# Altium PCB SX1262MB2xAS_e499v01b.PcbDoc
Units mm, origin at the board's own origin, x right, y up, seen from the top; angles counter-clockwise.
Board outline 65 x 53.3 mm, 4 copper layers (Top Layer, MidLayer1, MidLayer2, Bottom Layer), stack 0.986 mm thick; 64 components, 41 nets, 172 pads, 838 vias.
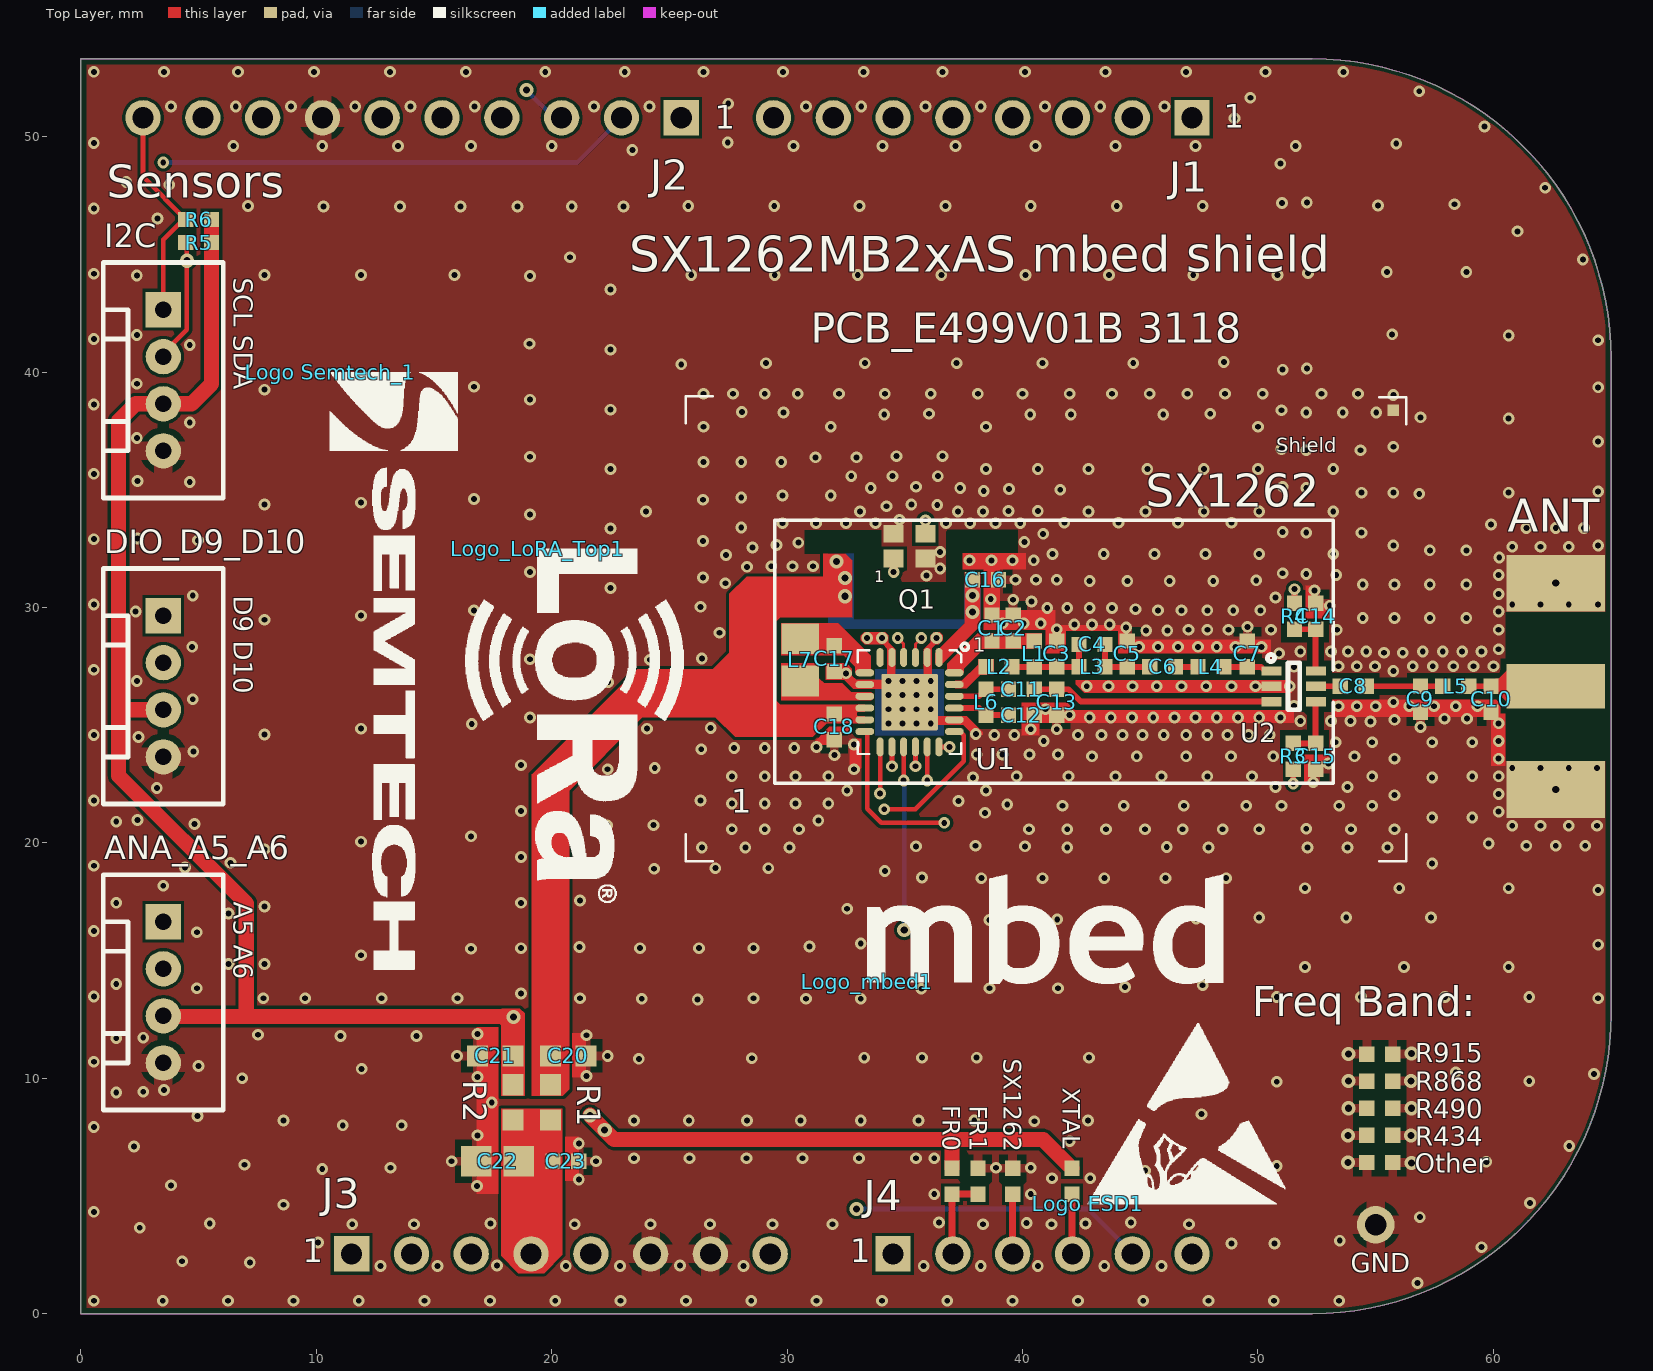
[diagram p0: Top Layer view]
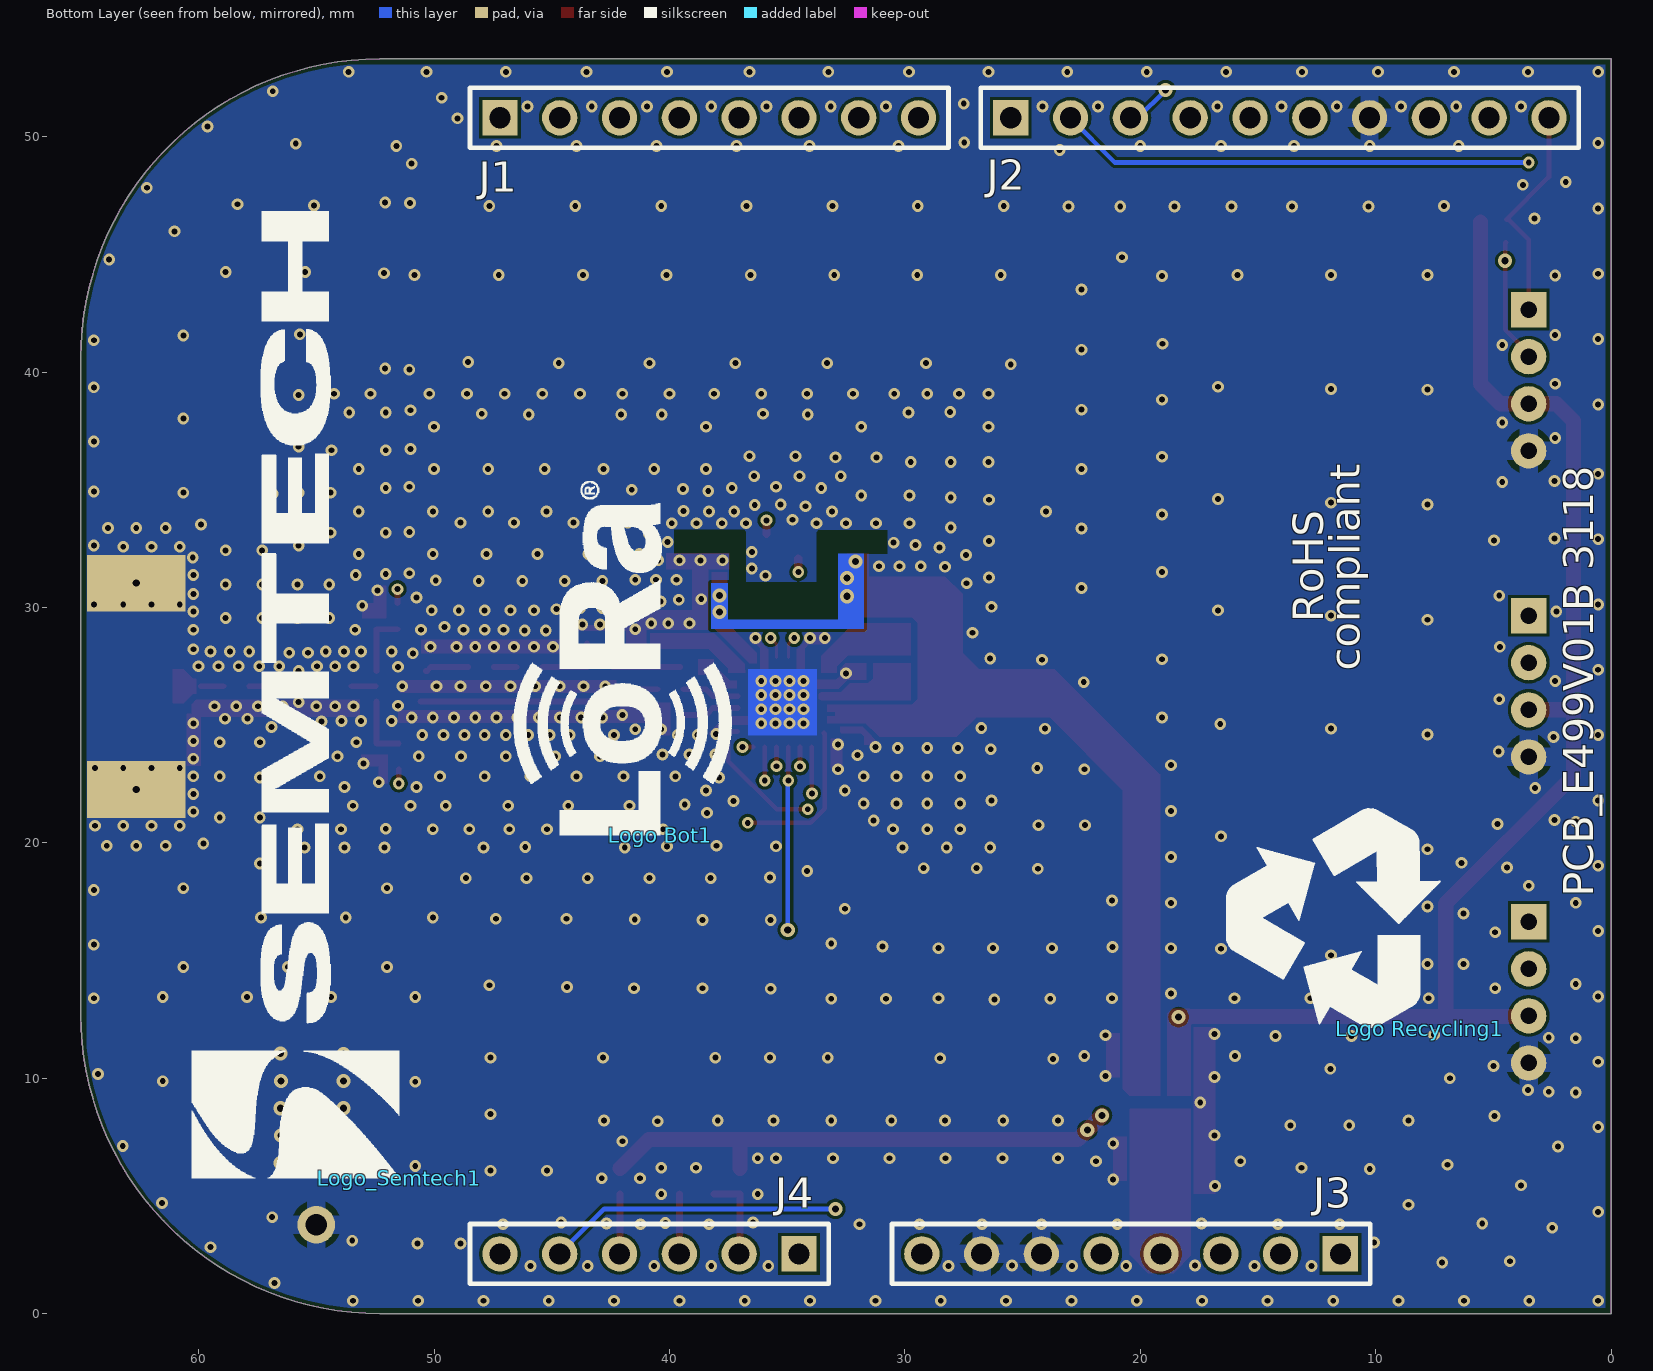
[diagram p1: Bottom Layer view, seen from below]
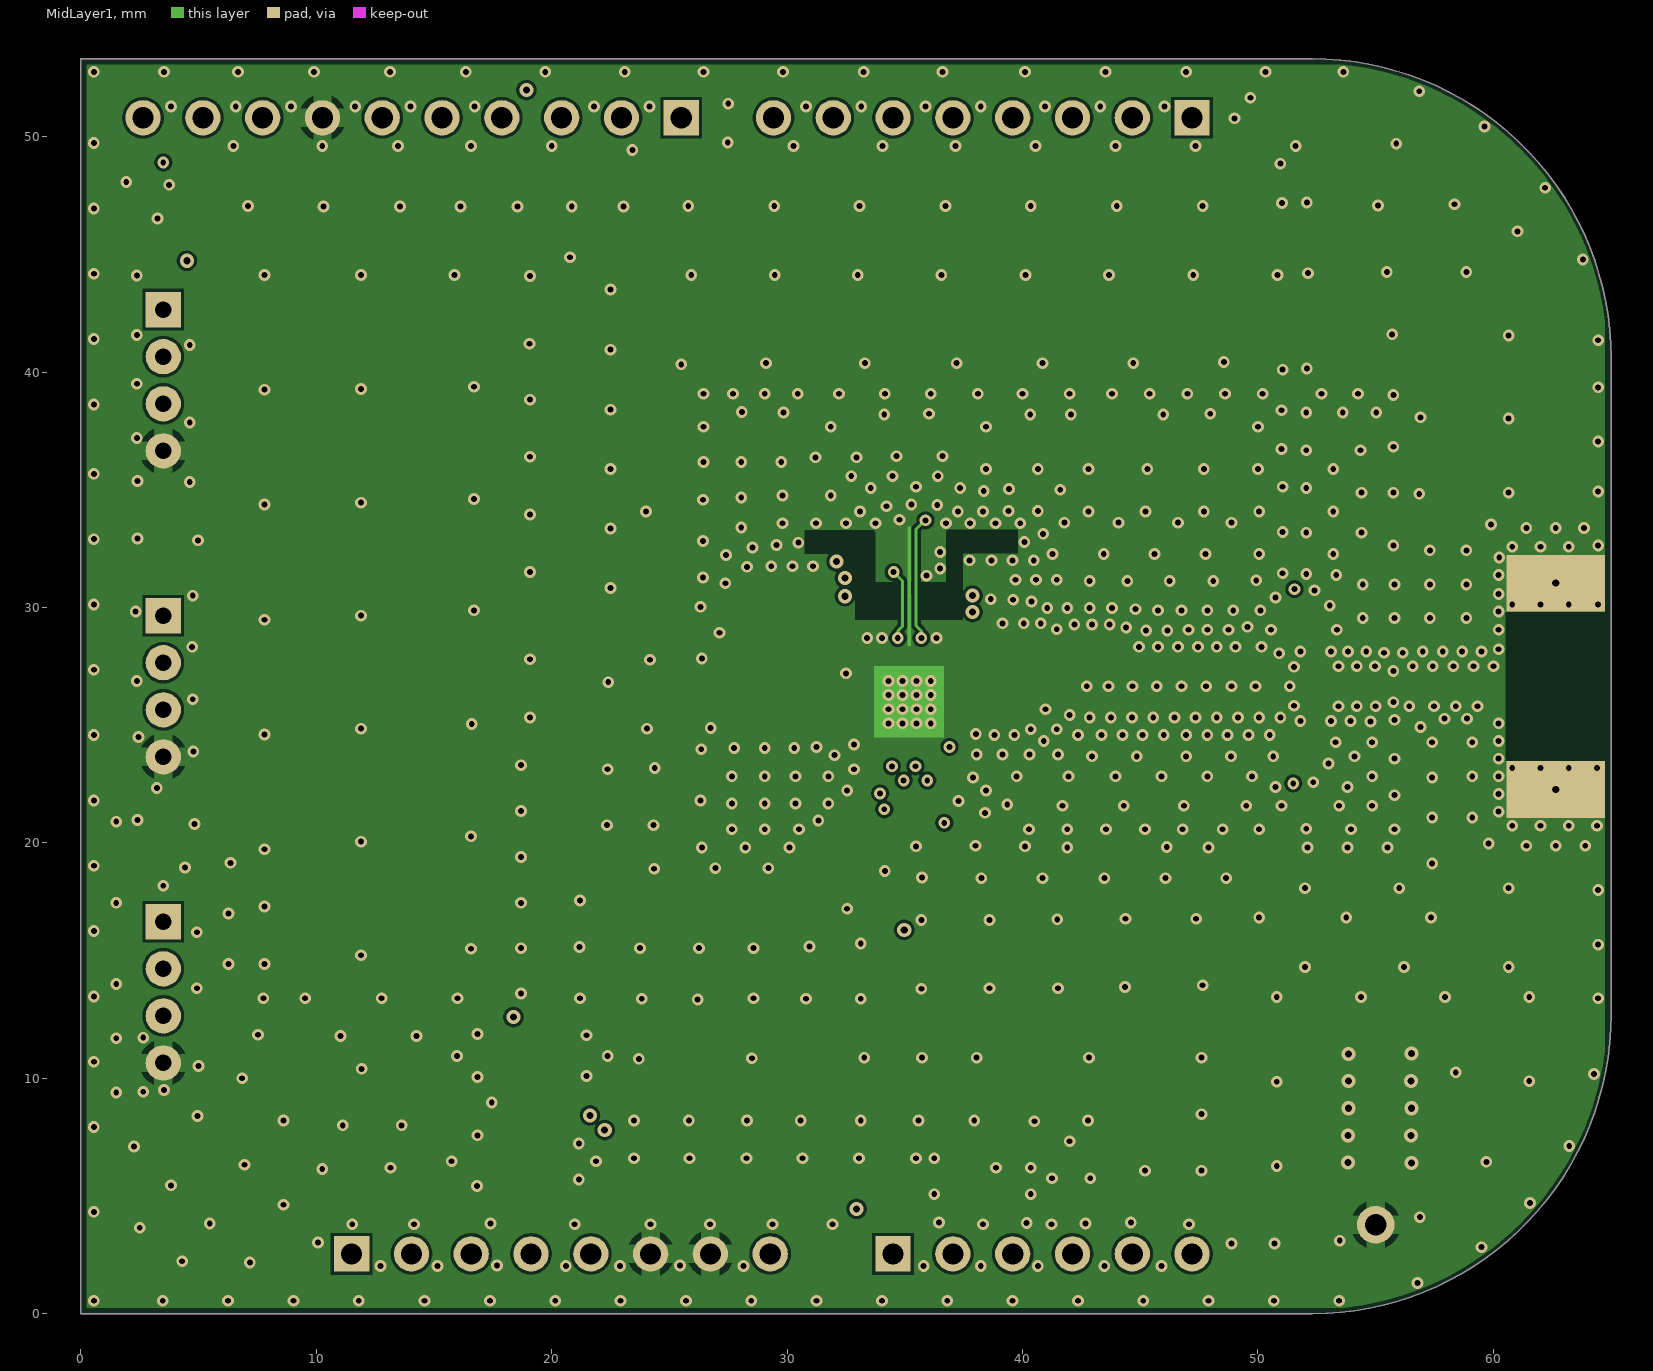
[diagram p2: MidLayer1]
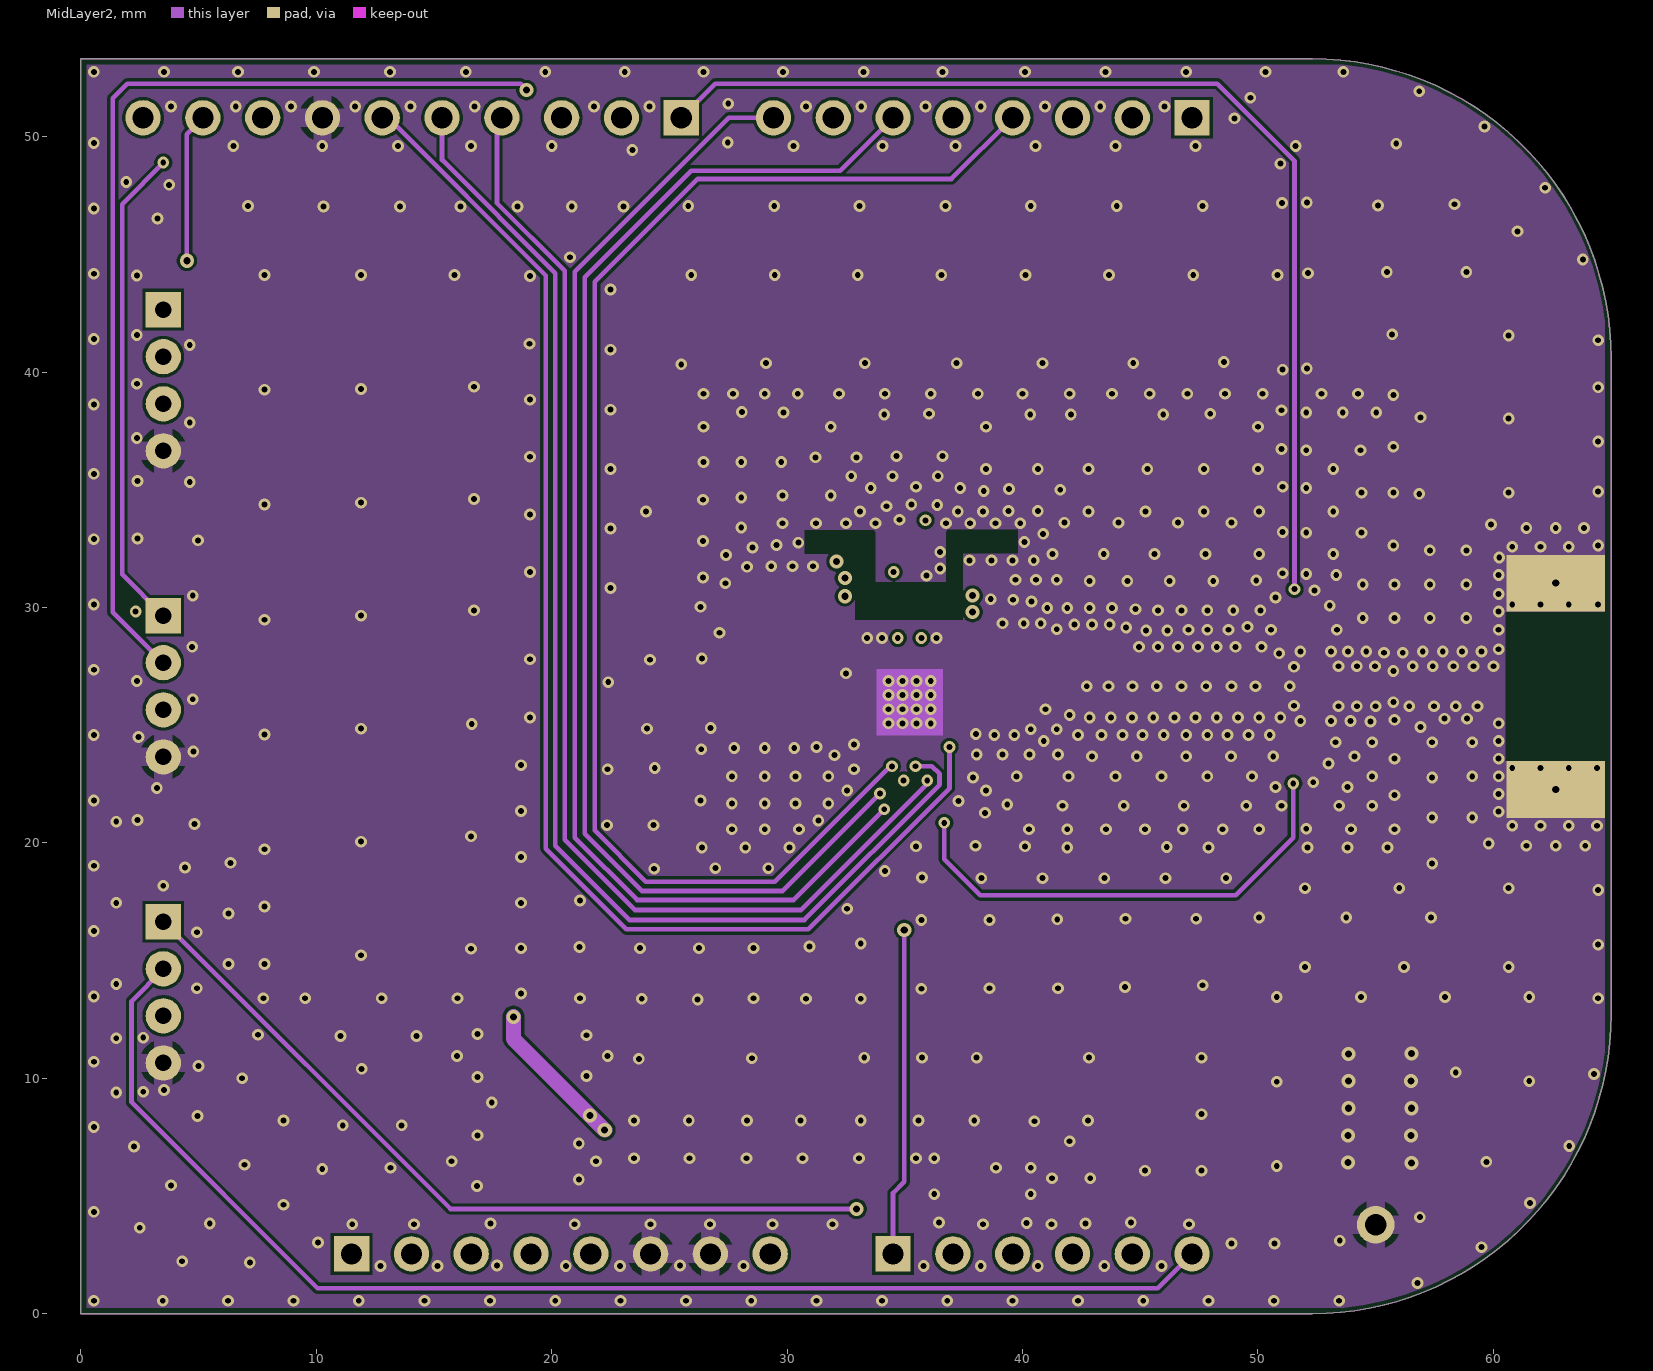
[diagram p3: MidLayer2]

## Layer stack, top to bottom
Top Solder: solder mask 0.0102, Solder Resist, Dk 3.5
Top Layer: signal copper 0.035
Dielectric1: core 0.15, FR-4, Dk 4.4
MidLayer1: signal copper 0.018
Dielectric3: prepreg 0.58, FR-4, Dk 4.4
MidLayer2: signal copper 0.018
Dielectric2: core 0.15, FR-4, Dk 4.4
Bottom Layer: signal copper 0.035
Bottom Solder: solder mask 0.0102, Solder Resist, Dk 3.5

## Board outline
0,0 52.3,0 ccw(c52.3,12.7) 65,12.7 65,40.6 ccw(c52.3,40.6) 52.3,53.3 0,53.3

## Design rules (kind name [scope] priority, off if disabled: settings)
Clearance Clearance_RF_GND [InNet('GND') And OnLayer('Top Layer') And (InPoly) vs InNet('NetL*') or InNet('NetC*') or InNet('NetU*')] p1: gap=0.25 ignorepadtopadclearanceinfootprint=FALSE except(0: Arc-Hole Track-Hole SMDPad-Hole THPad-Hole Via-Hole Fill-Hole Poly-Hole Region-Hole Text-Hole)
Clearance Clearance_GND_Keepout [InNet('GND') vs OnLayer('Keep-Out Layer')] p2: gap=0.15 ignorepadtopadclearanceinfootprint=FALSE except(0: Arc-Hole Track-Hole SMDPad-Hole THPad-Hole Via-Hole Fill-Hole Poly-Hole Region-Hole Text-Hole)
Clearance Clearance_GND [InNet('GND')] p3: gap=0.127 ignorepadtopadclearanceinfootprint=FALSE
Clearance [All] p4: gap=0.15 ignorepadtopadclearanceinfootprint=FALSE except(0: Arc-Hole Track-Hole SMDPad-Hole THPad-Hole Via-Hole Fill-Hole Poly-Hole Region-Hole Text-Hole)
ComponentClearance ComponentClearance_SMA_RFIO [InComponent('RFIO')] p1: gap=0.1 collisioncheckmode=3 verticalgap=0.1 showdistances=FALSE
ComponentClearance [All] p2: gap=0.2 collisioncheckmode=3 verticalgap=0.3 showdistances=FALSE
HoleSize [All] p1: absolutevalues=TRUE maxlimit=3.6 minlimit=0.25 maxpercent=80.000 minpercent=20.000
HoleToHoleClearance [All] p1: gap=0.2 allowstackedmicrovias=TRUE
MinimumSolderMaskSliver [All] p1: minsoldermaskwidth=0.04
PlaneClearance [All] p1: clearance=0.2
PlaneConnect [All] p1: planeconnectstyle=Direct reliefexpansion=0.508 reliefentries=4 reliefconductorwidth=0.254 reliefairgap=0.254
PolygonConnect "PolygonConnect SMD" [InNet('GND') vs HasFootprint('rlc_603_smd') or HasFootprint('rlc_402_smd') or hasFootprint('rlc_805_smd')  or hasFootprint('SOT353-5') or hasFootprint('VQFN24_4X4MM')] p1: connectstyle=Relief reliefconductorwidth=0.4 reliefentries=4 polygonreliefangle="90 Angle" airgapwidth=0.254
PolygonConnect PolygonConnect_comp_diverse [InNet('GND') vs HasFootprint('LGM676 LED') or  HasFootprint('BRIDGE_254MM') or  HasFootprint('pin_0.9mm')  or  HasFootprint('1125S-4P_connector')  or  HasFootprint('HDR1X10') or  HasFootprint('vqfn20_3x3mm') or    HasFootprint('HDR1X8')  or  HasFootprint('HDR1X6')] p2: connectstyle=Relief reliefconductorwidth=0.8 reliefentries=4 polygonreliefangle="90 Angle" airgapwidth=0.254
PolygonConnect PolygonConnect_all [All] p3: connectstyle=Direct reliefconductorwidth=0.6 reliefentries=4 polygonreliefangle="90 Angle" airgapwidth=0.254
RoomDefinition SX1262MB2xAS_e499v01b [InComponentClass('SX1262MB2xAS_e499v01b')] p1: confinementstyle=ConfineOut formatcopy=TRUE lockcomponents=FALSE outline -10.5,78.325 -10.55,78.375 -10.55,121.325 43.45,121.325 43.3,121.175 43.3,78.325
RoutingVias [All] p1: holewidth=0.3 width=0.6 viastyle="Through Hole" minholewidth=0.25 minwidth=0.5 maxholewidth=0.4 maxwidth=0.8
SilkToSilkClearance [All] p1: silktosilkclearance=0.05
SilkToSolderMaskClearance SilkscreenOverComponentPads [IsPad] p1: minsilkscreentomaskgap=0.05 clearancetoexposedcopper=TRUE
SolderMaskExpansion [All] p1: expansion=0.05
Width "Width GND" [InNet('GND')] p1: maxlimit=3 minlimit=0.2 preferedwidth=0.4
Width Width_VCC [InNet('VDD') or  InNet('VDISPLAY') or  InNet('VDD_MBED')  or  InNet('VUSB')  or  InNet('VDD_3V3')] p2: maxlimit=2 minlimit=0.2 preferedwidth=0.8
Width "Width All" [All] p3: maxlimit=2 minlimit=0.127 preferedwidth=0.2
22 further rules are at their usual default settings.

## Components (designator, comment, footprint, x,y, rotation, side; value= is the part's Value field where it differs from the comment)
ANA_A5_A6 "Header 4" 1125S-4P_connector 3.5,16.65 r270 top locked
ANT "SMA" SMA_end_launch_1.0mm_9.52mm 62.65,26.65 r0 top locked
C1 "Cap" RLC_402_SMD 38.7,29.125 r270 top value=NC
C2 "Cap" RLC_402_SMD 39.6,29.125 r270 top value=NC
C3 "Cap" RLC_402_SMD 41.45,28.025 r270 top value=NC
C4 "Cap" RLC_402_SMD 42.95,28.425 r180 top value=NC
C5 "Cap" RLC_402_SMD 44.45,28.025 r270 top value=NC
C6 "Cap" RLC_402_SMD 45.95,27.475 r180 top value=NC
C7 "Cap" RLC_402_SMD 49.55,28.025 r270 top value=NC
C8 "Cap" RLC_402_SMD 54.05,26.65 r180 top value=NC
C9 "Cap" RLC_402_SMD 56.9,26.1 r90 top value=NC
C10 "Cap" RLC_402_SMD 59.9,26.1 r90 top value=NC
C11 "Cap" RLC_402_SMD 39.95,26.525 r180 top value=NC
C12 "Cap" RLC_402_SMD 39.95,25.425 r180 top value=NC
C13 "Cap" RLC_402_SMD 41.45,25.975 r90 top value=NC
C14 "Cap" RLC_402_SMD 52.45,29.625 r90 top value=1nF
C15 "Cap" RLC_402_SMD 52.45,23.675 r270 top value=1nF
C16 "Cap" RLC_402_SMD 38.425,31.175 r180 top value=1uF
C17 "Cap" RLC_402_SMD 32,27.825 r90 top value=470nF
C18 "Cap" RLC_402_SMD 32,24.925 r90 top value=100nF
C20 "Cap" rlc_603_smd 20.7,10.95 r180 top value=1uF
C21 "Cap" rlc_603_smd 17.6,10.95 r0 top value=1uF
C22 "Cap" rlc_805_smd 17.7,6.475 r0 top value=10uF
C23 "Cap" rlc_402_smd 20.6,6.475 r180 top value=100nF
DIO_D9_D10 "Header 4" 1125S-4P_connector 3.5,29.65 r270 top locked
FR0 "Resistor" rlc_402_smd 37,5.625 r270 top value=1k
FR1 "Resistor" rlc_402_smd 38.111,5.625 r270 top value=NC
GND "Test Pin" pin_0.9mm 51.45,9.775 r90 top
I2C "Header 4" 1125S-4P_connector 3.5,42.65 r270 top locked
J1 "Header 8" HDR1X8 47.2,50.8 r180 bottom locked
J2 "Header 10" HDR1X10 25.5,50.8 r180 bottom locked
J3 "Header 8" HDR1X8 11.5,2.54 r0 bottom locked
J4 "Header 6" HDR1X6 34.5,2.54 r0 bottom locked
L1 "Inductor" RLC_402_SMD 40.5,28.025 r90 top value=0R
L2 "Inductor" RLC_402_SMD 39,27.475 r0 top value=0R
L3 "Inductor" RLC_402_SMD 42.95,27.475 r0 top value=0R
L4 "Inductor" RLC_402_SMD 48,27.475 r0 top value=0R
L5 "Inductor" RLC_402_SMD 58.4,26.65 r0 top value=0R
L6 "Inductor" RLC_402_SMD 38.45,25.975 r90 top value=0R
L7 "Inductor" "rlc_805_smd enlarged" 30.55,27.775 r270 top value=15uH
"Logo Bot1" "Logo symbol" "Logo LoRa Size4" 40.4,20.325 r90 bottom
"Logo ESD1" "Logo symbol" "Logo ESD" 42.775,4.674 r0 top
"Logo Recycling1" "Logo symbol" "Logo Recycling1" 8.125,12.1 r90 bottom
"Logo Semtech_1" "Logo symbol" logo_semtech_horiz_size3 10.6,40 r270 top locked
Logo_LoRA_Top1 "Logo symbol" "Logo LoRa Size4" 19.4,32.5 r270 top locked
Logo_mbed1 "Logo symbol" "logo mbed 2" 33.4,14.1 r0 top
Logo_Semtech1 "Logo symbol" logo_semtech_horiz_size4 51.475,5.75 r90 bottom
Other "Resistor" rlc_402_smd 55.175,6.425 r180 top value=NC
Q1 "Xtal" nd2016da 35.2,32.6 r0 top locked value=32.0MHz
R1 "Resistor" rlc_603_smd 19.95,8.975 r270 top value=0R
R2 "Resistor" rlc_603_smd 18.35,8.975 r270 top value=0R
R3 "Resistor" RLC_402_SMD 51.5,23.675 r270 top value=100R
R4 "Resistor" RLC_402_SMD 51.55,29.625 r90 top value=100R
R5 "Resistor" rlc_402_smd 5,45.5 r0 top value=3.3k
R6 "Resistor" rlc_402_smd 5,46.475 r0 top value=3.3k
R434 "Resistor" RLC_402_SMD 55.175,7.575 r0 top value=NC
R490 "Resistor" rlc_402_smd 55.175,8.725 r180 top value=NC
R868 "Resistor" RLC_402_SMD 55.175,9.875 r0 top value=NC
R915 "Resistor" RLC_402_SMD 55.175,11.025 r180 top value=NC
Shield "Logo symbol" "BMIS-209-F - Shield" 55.75,38.375 r180 top
SX1262 "Resistor" rlc_402_smd 39.58,5.625 r270 top value=10k
U1 "SX1262" VQFN24_4X4MM 35.2,25.975 r270 top
U2 "PE4259 RF Switch" SC70-6 51.525,26.65 r0 top
XTAL "Resistor" rlc_402_smd 42.1,5.625 r270 top value=1k

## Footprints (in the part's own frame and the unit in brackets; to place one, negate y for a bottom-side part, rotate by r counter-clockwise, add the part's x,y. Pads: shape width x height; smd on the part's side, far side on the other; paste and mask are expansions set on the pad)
1125S-4P_connector [mm] "Connector; Header; 4 Position; P/N: 1125S-4P; Manuf: TAIFENG"
  rect 1.5x1.5 hole 0.7 mask+0.05: 1(0,0)
  round 1.5 hole 0.7 mask+0.05: 2(2,0) 3(4,0) 4(6,0)
  silkscreen extent -2,-2.55 8,2.55, body extent -2,-2.55 8,2.55, height 2.95
"BMIS-209-F - Shield" [mm] "BMIS-209-F EMI Gasket - modif SolderMask - Standard Surface Mount Shields -  Laird Technologies"
  rect 0.5x0.5 smd paste-1 mask+0.05: 1(0,0)
  Mechanical 15 keep-out lines w1: 29.5,18.6 29.5,0 0,0 0,18.6 29.5,18.6
  silkscreen extent -0.55,-0.6 30.05,19.15, body extent -0.3,-0.3 0.3,0.3, height 0.8
HDR1X6 [mm] "Connector; Header; 6 Position"
  rect 1.5x1.5 hole 0.9: 1(0,0)
  round 1.5 hole 0.9: 2(2.54,0) 3(5.08,0) 4(7.62,0) 5(10.16,0) 6(12.7,0)
  silkscreen extent -1.27,-1.27 13.97,1.27, body extent -0.8,-0.8 13.5,0.8
HDR1X8 [mm] "Connector; Header; 8 Position"
  rect 1.5x1.5 hole 0.9: 1(0,0)
  round 1.5 hole 0.9: 2(2.54,0) 3(5.08,0) 4(7.62,0) 5(10.16,0) 6(12.7,0) 7(15.24,0) 8(17.78,0)
  silkscreen extent -1.27,-1.27 19.05,1.27, body extent -0.8,-0.8 18.58,0.8
HDR1X10 [mm] "Connector; Header; 10 Position"
  rect 1.5x1.5 hole 0.9: 1(0,0)
  round 1.5 hole 0.9: 2(2.54,0) 3(5.08,0) 4(7.62,0) 5(10.16,0) 6(12.7,0) 7(15.24,0) 8(17.78,0) 9(20.32,0) 10(22.86,0)
  silkscreen extent -1.27,-1.27 24.13,1.27, body extent -0.8,-0.8 23.66,0.8
"Logo ESD" [mm] "Logo ESD"
  silkscreen extent 0,0 8.38,7.67
"Logo LoRa Size4" [mm] "Logo LoRa Size4 - Top Overlay - 18x9.5mm - Registered"
  silkscreen extent 0,-3.05 15.04,6.2
"logo mbed 2" [mm] "logo mbed 2"
  silkscreen extent 0,-0.06 15.12,4.54
"Logo Recycling1" [mm] "Logo Recycling1"
  silkscreen extent 0.05,-0.88 9.36,8.2
logo_semtech_horiz_size3 [mm] "Logo semtech horizontal - size3 - L"
  silkscreen extent 0,0 25.4,5.41
logo_semtech_horiz_size4 [mm] "Logo semtech horizontal - size4 - XL"
  silkscreen extent 0,0 41.07,8.79
nd2016da [mm] "Crystal SMD 2.0x1.6mm"
  rect 0.85x0.75 smd mask+0.05: 1(-0.675,-0.525) 2(0.675,-0.525) 3(0.675,0.525) 4(-0.675,0.525)
  body extent -1,-0.8 1,0.8, height 1
pin_0.9mm [mm] "Generic Pin 0.9mm; 1 Lead"
  round 1.6 hole 0.9 mask+0.05: 1(-6,-3.55)
RLC_402_SMD [mm] "Chip SMD component 402; Body 1.0 x 0.5 mm (LxW typ)"
  rect 0.65x0.65 smd mask+0.05: 1(-0.55,0) 2(0.55,0)
  body extent -0.87,-0.33 0.87,0.33, height 0.8
rlc_402_smd [mm] "Chip SMD component 402; Body 1.0 x 0.5 mm (LxW typ)"
  rect 0.65x0.65 smd mask+0.05: 1(-0.55,0) 2(0.55,0)
  body extent -0.87,-0.33 0.87,0.33, height 0.8
rlc_603_smd [mm] "Chip SMD component 603; Body 1.6 x 0.8mm (LxW typ)"
  rect 0.9x0.9 smd paste+0 mask+0.05: 1(-0.75,0) 2(0.75,0)
rlc_805_smd [mm] "Chip SMD component 805; Body 2.0 x 1.25 mm (LxW typ)"
  rect 1.3x1.3 smd mask+0.05: 1(-0.9,0) 2(0.9,0)
"rlc_805_smd enlarged" [mm] "Chip SMD component 805; Body 2.0 x 1.25 mm (LxW typ)"
  rect 1.3x1.6 smd mask+0.05: 1(-0.9,0) 2(0.9,0)
SC70-6 [mm] "SC70 6-Leads, Body 2.0x1.25mm, Pitch 0.65mm"
  rect 0.85x0.4 smd mask+0.05: 1(-0.95,0.65) 2(-0.95,0) 3(-0.95,-0.65) 4(0.95,-0.65) 5(0.95,0) 6(0.95,0.65)
  silkscreen extent -1.12,-1 0.25,1.35, body extent -0.63,-1 0.63,1, height 1.45
SMA_end_launch_1.0mm_9.52mm [mm] "SMA end launch for 1.0mm PCB thickness; 9.52mm"
  rect 4.2x1.905 smd mask+0.05: 1(0,0)
  rect 4.2x2.413 hole 0.3 mask+0.05: 2(0,-4.38) 2(0,4.38)
VQFN24_4X4MM [mm] "24 Leads, Body 4.0x4.0mm, Pitch 0.50mm, VQFN24"
  oval 0.8x0.3 smd mask+0.05: 1(-1.9,1.25) 2(-1.9,0.75) 3(-1.9,0.25) 4(-1.9,-0.25) 5(-1.9,-0.75) 6(-1.9,-1.25) 13(1.9,-1.25) 14(1.9,-0.75) 15(1.9,-0.25) 16(1.9,0.25) 17(1.9,0.75) 18(1.9,1.25)
  oval 0.3x0.8 smd mask+0.05: 7(-1.25,-1.9) 8(-0.75,-1.9) 9(-0.25,-1.9) 10(0.25,-1.9) 11(0.75,-1.9) 12(1.25,-1.9) 19(1.25,1.9) 20(0.75,1.9) 21(0.25,1.9) 22(-0.25,1.9) 23(-0.75,1.9) 24(-1.25,1.9)
  rrect5% 2.4x2.4 smd paste-2.5 mask+0.05: 25(0,0)
  Mechanical 15 keep-out lines w0.1: 2.5,-2.5 2.5,2.5 -2.5,2.5 -2.5,-2.5 2.5,-2.5
  silkscreen extent -2.5,-2.2 2.2,2.5, body extent -2,-2 2,2, height 1

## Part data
ANA_A5_A6 DIO_D9_D10 I2C: "Header, 4-Pin"
ANT: "SMA Straight Connector"
C1 C2 C3 C4 C5 C6 C7 C8 C9 C10 C11 C12 C13 C14 C15 C16 C17 C18 C20 C21 C22 C23: "Capacitor SMD"
FR0 FR1 Other R1 R2 R3 R4 R5 R6 R434 R490 R868 R915 SX1262 XTAL: "Resistor SMD - IEC symbol version"
GND: library part test_pin
J1 J3: "Header, 8-Pin"
J2: "Header, 10-Pin"
J4: "Header, 6-Pin"
L1 L2 L3 L4 L5 L6 L7: "Inductor SMD"
"Logo Bot1" "Logo ESD1" "Logo Recycling1" "Logo Semtech_1" Logo_LoRA_Top1 Logo_mbed1 Logo_Semtech1: library part Logo, "Schematic symbol for Logo"
Q1: library part "Xtal GND", "Crystal with GND pins"
Shield: library part Shield, "Shield - EMI Gasket - Standard Surface Mount Shields"
U1: library part SX126x, "SX1262- Ultra low power RF transceiver"
U2: "PE4259 Peregrine RF Switch"

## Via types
v1: diameter 0.5, hole 0.25, Top Layer to Bottom Layer, tented both sides, 816 vias
v2: diameter 0.6, hole 0.3, Top Layer to Bottom Layer, tented both sides, 22 vias

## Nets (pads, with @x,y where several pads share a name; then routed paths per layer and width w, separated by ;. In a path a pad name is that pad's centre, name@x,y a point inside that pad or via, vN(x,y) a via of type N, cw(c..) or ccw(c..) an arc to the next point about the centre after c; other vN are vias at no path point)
A5: ANA_A5_A6.1 J4.5 | length 47
  MidLayer2 w0.2: ANA_A5_A6.1 15.7,4.45 v2(32.95,4.45)
  Bottom Layer w0.2: v2(32.95,4.45) 42.775,4.45 J4.5@44.675,2.55
A6: ANA_A5_A6.2 J4.6 | length 55.2
  MidLayer2 w0.2: ANA_A5_A6.2@3.525,14.65 2.15,13.275 2.15,8.975 10.05,1.075 45.735,1.075 J4.6
ANT_SW: J2.1 R4.2 | length 46.8
  Top Layer w0.25: R4.2 v1(51.55,30.775)
  MidLayer2 w0.2: J2.1 26.95,52.25 48.275,52.25 51.55,48.975 v1(51.55,30.775)
BUSY: J1.4 U1.14 | length 60.3
  Top Layer w0.2: v1(34.45,23.25) U1.14
  MidLayer2 w0.2: v1(34.45,23.25) 34.375,23.25 29.475,18.35 24,18.35 21.825,20.525 21.825,43.825 26.2,48.2 36.98,48.2 J1.4
D9: DIO_D9_D10.1 J2.2 | length 41
  MidLayer2 w0.2: DIO_D9_D10.1 1.75,31.4 1.75,47.125 v1@3.55,48.925
  Bottom Layer w0.2: v1(3.5,48.9) 21.075,48.9 J2.2@22.975,50.8
D10: DIO_D9_D10.2 J2.3 | length 45.2
  MidLayer2 w0.2: DIO_D9_D10.2@3.5,27.796 DIO_D9_D10.2 1.35,29.8 1.35,51.625 1.975,52.25 18.675,52.25 18.925,52 v2(18.925,51.975)
  Bottom Layer w0.2: v2(18.925,51.975) 20.1,50.8 J2.3@20.4,50.8 ; J2.3@20.15,50.775 J2.3@20.4,50.775
DIO1: J1.6 U1.13 | length 56.8
  Top Layer w0.2: v1(33.95,22.1) U1.13
  MidLayer2 w0.2: v1(33.95,22.1) 29.8,17.95 23.838,17.95 21.4,20.388 21.4,44.025 25.925,48.55 32.25,48.55 J1.6 ; v1@34.025,22.15 v1@34.05,22.15
DIO2: R3.2 U1.12 | length 27.7
  Top Layer w0.2: U1.12@33.437,24.663 33.4,24.625 33.4,21.446 33.996,20.85 v1(36.675,20.85) v1@36.625,20.85
  Top Layer w0.25: v1(51.5,22.525) R3.2
  MidLayer2 w0.2: v1(36.675,20.85) 36.675,19.3 38.2,17.775 49.05,17.775 49.1,17.825 51.5,20.225 v1(51.5,22.525)
DIO3: U1.6
GND: ANA_A5_A6.4 ANT.2 C1.1 C2.1 C3.1 C5.1 C7.1 C9.1 C10.1 C12.1 C13.1 C14.2 C15.2 C16.1 C17.1 C18.1 C20.1 C21.1 C22.1 C23.1 DIO_D9_D10.4 FR1.1 GND.1 I2C.4 J2.7 J3.6 J3.7 Other.1 Other.2 Q1.2 Q1.4 R434.1 R434.2 R490.1 R490.2 R868.1 R868.2 R915.1 R915.2 Shield.1 SX1262.1 U1.2 U1.5 U1.8 U1.20 U1.25 U2.2 | length 4.1
  Top Layer w0.3: U1.8 U1.25@34.3,26.725 ; U1.25@34.45,26.825 U1.5 ; U1.25@35.95,26.875 U1.2 ; U1.25@36.1,25.175 36.15,25.225 U1.20
  other v1: 0.55,0.55 3.475,0.55 6.25,0.55 9.025,0.55 11.8,0.55 14.6,0.55 17.375,0.55 20.15,0.55 22.925,0.55 25.7,0.55 28.475,0.55 31.25,0.55 34.025,0.55 36.8,0.55 39.575,0.55 42.35,0.55 45.125,0.55 47.9,0.55 50.675,0.55 53.45,0.55 56.775,1.3 12.725,2.025 15.15,2.025 20.6,2.025 22.9,2.025 28.15,2.025 35.8,2.025 38.225,2.025 40.65,2.025 43.475,2.025 45.9,2.025 17.675,2.05 25.45,2.05 7.175,2.175 4.3,2.225 59.5,2.825 48.875,2.975 50.7,2.975 10.075,3.025 53.475,3.1 2.5,3.65 11.525,3.8 14.15,3.8 20.975,3.8 24.2,3.8 26.725,3.8 29.375,3.8 31.925,3.8 38.325,3.8 41.225,3.8 47.075,3.8 5.475,3.825 17.4,3.825 42.675,3.825 40.175,3.85 36.45,3.875 44.6,3.875 56.875,4.1 0.55,4.325 8.6,4.625 61.55,4.7 36.25,5.075 40.35,5.075 16.825,5.425 3.825,5.45 21.15,5.7 41.25,5.75 42.875,5.75 45.2,6.075 47.6,6.075 10.25,6.15 13.15,6.2 38.875,6.2 40.35,6.2 50.8,6.275 6.95,6.325 59.7,6.45 15.75,6.475 21.875,6.475 23.5,6.6 25.85,6.6 28.275,6.6 30.65,6.6 33.05,6.6 35.475,6.6 36.25,6.6 2.25,7.1 63.225,7.125 21.15,7.225 42,7.325 16.85,7.575 0.55,7.925 11.125,8 13.625,8 40.5,8.175 8.6,8.2 23.5,8.2 25.825,8.2 28.3,8.2 30.575,8.2 33.125,8.2 35.575,8.2 37.95,8.2 42.775,8.2 4.95,8.4 47.6,8.475 17.45,8.975 1.5,9.4 2.65,9.425 3.525,9.5 50.8,9.85 61.525,9.875 6.85,10 16.85,10.05 21.475,10.1 64.275,10.175 58.4,10.25 11.925,10.4 5,10.525 0.55,10.7 23.7,10.825 28.5,10.85 33.275,10.875 35.725,10.875 38.05,10.875 42.825,10.875 47.6,10.875 15.975,10.95 22.375,10.95 1.5,11.7 2.65,11.725 11.025,11.8 14.25,11.8 21.475,11.825 7.525,11.85 16.85,11.875 26.2,13.35 23.825,13.375 30.8,13.375 33.125,13.375 7.75,13.4 9.525,13.4 12.775,13.4 16,13.4 21.2,13.4 28.575,13.4 64.45,13.4 50.8,13.45 54.375,13.45 57.95,13.45 61.525,13.45 0.55,13.475 18.7,13.6 35.7,13.8 4.925,13.825 38.6,13.825 41.5,13.825 44.35,13.875 47.65,13.95 1.5,14 52,14.725 56.2,14.725 60.65,14.725 6.275,14.85 7.8,14.85 11.9,15.225 16.575,15.5 18.7,15.525 23.75,15.525 26.25,15.525 28.575,15.525 21.175,15.575 30.95,15.6 64.45,15.675 33.125,15.725 4.925,16.2 0.55,16.25 35.7,16.725 38.6,16.725 41.475,16.75 44.375,16.775 47.375,16.775 50.05,16.825 53.75,16.825 57.35,16.825 6.275,17 32.55,17.2 7.8,17.3 1.5,17.45 18.7,17.45 21.2,17.55 64.45,18 52,18.075 56,18.075 60.65,18.075 3.5,18.175 38.25,18.5 40.85,18.5 43.475,18.5 46.075,18.5 48.65,18.5 35.725,18.525 34.15,18.8 24.35,18.9 26.95,18.925 29.2,18.925 4.425,18.95 0.55,19.025 57.4,19.125 6.35,19.15 18.7,19.4 7.8,19.725 26.375,19.8 28.225,19.8 30.1,19.8 41.9,19.8 47.9,19.8 52.1,19.8 53.8,19.8 55.5,19.8 46.125,19.825 35.475,19.85 40.1,19.85 38,19.875 61.4,19.875 62.65,19.875 63.9,19.875 59.8,19.975 11.9,20.05 16.575,20.275 27.65,20.575 29.05,20.575 30.5,20.575 40.275,20.575 41.9,20.575 43.55,20.575 45.2,20.575 46.8,20.575 48.5,20.575 50.05,20.575 53.95,20.575 55.8,20.575 52.05,20.6 60.8,20.725 62,20.725 63.2,20.725 64.4,20.725 22.35,20.75 24.325,20.75 4.825,20.8 1.5,20.9 31.325,20.95 2.4,20.975 57.4,21.075 59.1,21.075 38.4,21.275 60.225,21.325 18.7,21.35 41.7,21.575 44.3,21.575 46.85,21.575 49.5,21.575 51,21.575 53.45,21.575 54.85,21.575 39.35,21.625 27.65,21.675 29.05,21.675 30.35,21.675 31.75,21.675 37.275,21.775 0.55,21.8 26.325,21.8 55.8,22.025 60.225,22.075 32.55,22.225 38.45,22.225 3.225,22.325 50.75,22.375 53.8,22.375 52.35,22.575 37.9,22.775 57.4,22.775 27.65,22.825 29.05,22.825 30.35,22.825 31.75,22.825 39.75,22.825 41.95,22.825 43.95,22.825 45.9,22.825 47.85,22.825 49.75,22.825 54.85,22.825 59.1,22.825 60.225,22.825 22.375,23.125 32.837,23.125 24.375,23.175 60.8,23.175 62,23.175 63.2,23.175 64.4,23.175 18.7,23.3 53,23.375 55.8,23.575 60.225,23.575 42.95,23.675 44.85,23.675 46.95,23.675 48.85,23.675 50.65,23.675 54.1,23.675 32.011,23.725 38.05,23.75 39.15,23.75 40.3,23.75 41.5,23.75 4.775,23.875 26.35,23.975 27.75,24.025 29.05,24.025 30.3,24.025 31.25,24.075 32.837,24.175 53.3,24.275 54.85,24.275 57.4,24.275 59.1,24.275 40.9,24.325 60.225,24.325 2.45,24.5 0.55,24.575 38.8,24.575 39.65,24.575 42.35,24.575 43.35,24.575 44.25,24.575 45.1,24.575 46,24.575 46.95,24.575 47.85,24.575 48.7,24.575 49.6,24.575 50.5,24.575 7.8,24.6 38.016,24.625 40.35,24.825 41.45,24.825 11.9,24.85 24.05,24.85 26.75,24.875 56.9,24.925 16.6,25.05 34.3,25.075 34.9,25.075 35.5,25.075 36.1,25.075 60.225,25.075 54.775,25.15 51.8,25.175 53.1,25.175 53.925,25.175 55.8,25.225 57.925,25.275 58.875,25.275 19.075,25.325 42.85,25.325 43.75,25.325 44.65,25.325 45.55,25.325 46.45,25.325 47.35,25.325 48.25,25.325 49.15,25.325 50.05,25.325 50.95,25.325 42,25.425 34.3,25.675 34.9,25.675 35.5,25.675 36.1,25.675 40.975,25.675 53.425,25.8 54.2,25.8 55,25.8 56.425,25.8 57.475,25.8 58.4,25.8 59.325,25.8 51.525,25.825 55.75,25.975 4.75,26.1 34.3,26.275 34.9,26.275 35.5,26.275 36.1,26.275 42.725,26.65 43.65,26.65 44.675,26.65 45.7,26.65 46.75,26.65 47.8,26.65 48.875,26.65 49.9,26.65 51.35,26.65 22.4,26.825 2.375,26.875 34.3,26.875 34.9,26.875 35.5,26.875 36.1,26.875 32.5,27.2 55.75,27.3 0.55,27.35 51.525,27.475 53.425,27.5 54.2,27.5 54.975,27.5 56.575,27.5 57.425,27.5 58.3,27.5 59.15,27.5 60,27.5 24.175,27.775 19.075,27.8 26.375,27.825 50.9,28.05 55.35,28.075 56.15,28.075 51.8,28.125 53.1,28.125 53.825,28.125 54.6,28.125 57,28.125 57.85,28.125 58.675,28.125 59.5,28.125 60.225,28.225 4.725,28.325 44.95,28.325 45.75,28.325 46.6,28.325 47.45,28.325 48.25,28.325 49.05,28.325 50.15,28.325 33.4,28.7 34.025,28.7 36.35,28.7 27.125,28.925 45.25,29.025 46.15,29.025 47.05,29.05 47.85,29.05 48.75,29.05 50.55,29.05 53.35,29.05 60.225,29.05 41.45,29.075 44.4,29.15 49.55,29.175 42.2,29.275 42.95,29.275 43.7,29.275 39.15,29.325 40.05,29.325 40.775,29.325 7.8,29.475 54.45,29.55 55.8,29.55 57.3,29.55 58.85,29.55 11.9,29.65 2.325,29.825 60.225,29.825 16.7,29.875 45.75,29.875 46.75,29.875 47.85,29.875 48.95,29.875 50.1,29.875 44.8,29.925 41.05,29.975 41.9,29.975 42.85,29.975 43.8,29.975 26.325,30.025 53.05,30.075 0.55,30.125 60.8,30.125 62,30.125 63.2,30.125 64.45,30.125 40.375,30.255 39.6,30.325 38.65,30.35 50.75,30.425 4.75,30.5 60.225,30.575 52.4,30.725 22.5,30.825 54.45,30.975 55.8,30.975 57.3,30.975 58.85,30.975 27.375,31.025 42.85,31.125 44.45,31.125 46.25,31.125 48.1,31.125 49.925,31.15 39.7,31.175 40.575,31.175 41.45,31.175 26.425,31.275 35.925,31.35 53.325,31.375 60.225,31.375 52.05,31.425 51.05,31.45 19.075,31.5 36.5,31.65 28.3,31.725 29.325,31.75 30.225,31.75 31.1,31.75 37.75,32 38.675,32 39.575,32 40.475,32 60.25,32.125 27.4,32.225 41.275,32.275 43.45,32.275 45.6,32.275 47.775,32.275 50.05,32.275 53.2,32.275 36.5,32.35 57.3,32.425 58.85,32.425 28.525,32.55 60.8,32.575 62,32.575 63.2,32.575 55.75,32.625 64.45,32.625 29.55,32.65 30.475,32.75 40.075,32.775 26.425,32.825 4.975,32.85 0.55,32.9 2.4,32.925 40.875,33.125 52.05,33.175 54.4,33.175 51.05,33.2 22.5,33.35 61.4,33.375 62.65,33.375 63.85,33.375 28.05,33.4 59.9,33.525 29.8,33.575 31.225,33.575 32.5,33.575 33.75,33.575 36.75,33.575 37.775,33.575 38.85,33.575 39.9,33.575 41.775,33.6 44.075,33.6 46.6,33.6 48.875,33.6 34.775,33.725 19.075,33.95 24,34.075 33.1,34.075 37.25,34.075 38.325,34.075 42.8,34.075 45.225,34.075 47.7,34.075 50.05,34.075 53.2,34.075 39.4,34.1 40.65,34.1 34.225,34.3 36.375,34.35 7.8,34.375 35.275,34.375 11.9,34.45 26.425,34.575 16.7,34.6 28.05,34.675 29.8,34.75 31.85,34.75 56.85,34.825 54.4,34.875 55.75,34.875 60.65,34.875 64.45,34.925 38.35,34.95 41.6,35 39.425,35.025 33.55,35.075 37.35,35.075 52.05,35.075 35.475,35.125 51.05,35.125 4.625,35.325 2.4,35.375 32.725,35.575 34.475,35.575 36.4,35.575 0.55,35.675 22.5,35.875 38.45,35.875 40.65,35.875 42.8,35.875 45.3,35.875 47.7,35.875 50,35.875 53.2,35.875 26.45,36.175 28.05,36.175 29.75,36.175 31.2,36.375 32.95,36.375 19.075,36.4 34.65,36.425 36.6,36.425 52.05,36.675 54.35,36.675 51,36.725 55.75,36.825 64.45,37.05 2.375,37.2 26.45,37.675 31.85,37.675 38.45,37.675 50,37.675 4.625,37.85 60.65,38.025 56.9,38.075 34.125,38.2 40.325,38.2 42.05,38.2 45.975,38.2 36.025,38.225 47.975,38.225 29.85,38.275 52.05,38.275 53.6,38.275 55.025,38.275 28.075,38.3 51,38.375 22.5,38.4 0.55,38.625 19.075,38.825 55.75,39.025 26.45,39.075 27.7,39.075 29.05,39.075 30.45,39.075 32.2,39.075 34.15,39.075 36.1,39.075 38.1,39.075 40,39.075 42,39.075 43.8,39.075 45.4,39.075 47,39.075 48.6,39.075 50.2,39.075 52.7,39.075 54.25,39.075 7.8,39.25 11.9,39.275 64.45,39.35 16.7,39.375 2.375,39.5 51.05,40.1 52.075,40.15 25.5,40.325 29.1,40.375 33.3,40.375 37.2,40.375 40.85,40.375 44.7,40.375 48.55,40.425 22.5,40.95 4.625,41.15 19.05,41.2 64.45,41.35 0.55,41.4 60.65,41.55 2.375,41.575 55.7,41.6 22.5,43.5 19.075,44.075 2.375,44.1 7.8,44.125 11.9,44.125 15.875,44.125 25.925,44.125 29.475,44.125 33,44.125 36.55,44.125 40.125,44.125 43.675,44.125 47.25,44.125 50.825,44.125 0.55,44.175 52.125,44.2 55.475,44.25 58.85,44.25 63.8,44.775 20.775,44.875 61.025,45.975 3.25,46.525 0.55,46.95 10.3,47.025 13.55,47.025 16.125,47.025 18.55,47.025 20.85,47.025 23.05,47.025 7.1,47.05 25.8,47.05 29.45,47.05 33.075,47.05 36.725,47.05 40.35,47.05 44,47.05 47.65,47.05 55.1,47.075 58.35,47.125 51.025,47.175 52.075,47.2 62.2,47.825 3.75,47.95 1.925,48.075 50.95,48.85 23.425,49.425 6.475,49.6 10.25,49.6 13.475,49.6 16.575,49.6 20,49.6 30.275,49.6 34.05,49.6 37.15,49.6 40.55,49.6 43.95,49.6 47.35,49.6 51.6,49.6 55.875,49.7 0.55,49.725 27.475,49.75 59.625,50.425 49,50.775 3.825,51.275 6.575,51.275 8.925,51.275 11.65,51.275 14,51.275 16.725,51.275 21.8,51.275 24.15,51.275 30.8,51.275 33.15,51.275 35.875,51.275 38.225,51.275 40.95,51.275 43.3,51.275 46.025,51.275 27.5,51.4 49.675,51.65 56.85,51.925 0.55,52.75 3.525,52.75 6.675,52.75 9.9,52.75 13.125,52.75 16.35,52.75 19.725,52.75 23.1,52.75 26.45,52.75 29.825,52.75 33.25,52.75 36.6,52.75 40.1,52.75 43.525,52.75 46.95,52.75 50.325,52.75 53.625,52.75
  other v2: 56.525,6.4 53.825,6.425 53.825,7.575 56.5,7.575 53.85,8.725 56.525,8.725 53.85,9.875 56.5,9.875 53.85,11.025 56.525,11.05
I2C_SCL: I2C.1 J2.10 R6.1 | length 9.4
  Top Layer w0.2: J2.10 2.64,48.285 R6.1 4.35,46.475 3.5,45.625 I2C.1
I2C_SDA: I2C.2 J2.9 R5.1 | length 11.6
  Top Layer w0.2: I2C.2 3.5,40.796 4.5,41.796 v2(4.5,44.725) 4.5,45.5 R5.1
  MidLayer2 w0.2: v2(4.5,44.725) 4.5,50.1 J2.9@5.175,50.775
MISO: J2.5 U1.16 | length 55.4
  Top Layer w0.2: v1(35.45,23.253) U1.16
  MidLayer2 w0.2: J2.5 15.34,49.01 20.15,44.2 20.15,19.875 23.3,16.725 30.734,16.725 36.475,22.466 36.475,22.925 36.147,23.253 v1(35.45,23.253)
MOSI: J2.4 U1.17 | length 52.4
  Top Layer w0.2: v1@35.952,22.625 v1(35.952,22.65) U1.17@35.952,24.073
  MidLayer2 w0.2: J2.4 17.675,50.595 17.675,47.175 20.55,44.3 20.55,20.125 23.525,17.15 30.6,17.15 31.2,17.75 35.95,22.5 v1@35.95,22.65
NetANT_1: ANT.1 C10.2 L5.2 | length 1
  Top Layer w0.25: L5.2 C10.2
NetC3_2: C3.2 C4.2 L1.1 L2.2 L3.1 | length 3.8
  Top Layer w0.25: L2.2 L1.1 C3.2 L3.1 C4.2
NetC4_1: C4.1 C5.2 C6.2 L3.2 | length 2.9
  Top Layer w0.25: C4.1@43.5,28.475 C4.1 L3.2 C5.2 C6.2
NetC6_1: C6.1 L4.1 | length 1
  Top Layer w0.25: C6.1 L4.1@47.45,27.475
NetC7_2: C7.2 L4.2 U2.1 | length 1.9
  Top Layer w0.25: L4.2 C7.2 50.125,27.475 50.3,27.3 U2.1@50.35,27.3
NetC8_1: C8.1 C9.2 L5.1 | length 3.3
  Top Layer w0.25: C8.1 C9.2 L5.1
NetC8_2: C8.2 U2.5 | length 1
  Top Layer w0.25: U2.5 C8.2
NetC11_1: C11.1 C13.2 U2.3 | length 10.3
  Top Layer w0.25: C11.1 C13.2 41.95,26.525 42.475,26 U2.3
NetC11_2: C11.2 L6.2 U1.22 | length 2.4
  Top Layer w0.25: U1.22 38.15,26.225 L6.2 C11.2
NetC12_2: C12.2 L6.1 U1.21 | length 2.4
  Top Layer w0.25: U1.21 38.15,25.725 L6.1 C12.2
NetC14_1: C14.1 R4.1 U2.6 | length 2.7
  Top Layer w0.25: R4.1 C14.1 U2.6@52.45,27.3
NetC15_1: C15.1 R3.1 U2.4 | length 2.7
  Top Layer w0.25: R3.1 C15.1 U2.4@52.45,26
NetC17_2: C17.2 L7.1 U1.7
NetFR0_2: FR0.2 FR1.2 J4.2 | length 3.7
  Top Layer w0.3: J4.2 37,2.58 FR0.2 FR1.2
NetJ4_3: J4.3 SX1262.2 | length 2.5
  Top Layer w0.3: J4.3 SX1262.2
NetL2_1: L2.1 U1.23
NetL7_2: L7.2 U1.9
NSS: J1.8 U1.19 | length 56.9
  Top Layer w0.2: v1(34.127,21.426) 35.451,21.426 37.5,23.475 37.5,24.575 37.35,24.725 U1.19
  MidLayer2 w0.2: J1.8 27.525,50.8 20.975,44.25 20.975,20.225 23.625,17.575 30.275,17.575 34.125,21.425 v1(34.127,21.426) 34.127,21.302 v1@34.125,21.3
OPT: J4.4 XTAL.2 | length 2.5
  Top Layer w0.3: XTAL.2 42.1,2.56 J4.4
SCK: J2.6 U1.18 | length 57.3
  Top Layer w0.2: U1.18 v1(36.9,24.075)
  MidLayer2 w0.2: J2.6 12.85,50.8 12.875,50.775 13.075,50.775 19.75,44.1 19.75,19.75 23.175,16.325 30.9,16.325 36.9,22.325 v1(36.9,24.075)
SX_NRESET: J4.1 U1.15 | length 21.8
  Top Layer w0.2: v1(34.95,22.65) U1.15
  MidLayer2 w0.2: J4.1 34.5,5.125 34.975,5.6 v2(34.975,16.3)
  Bottom Layer w0.2: J4.1 J4.1@34.525,2.565 ; v1(34.95,22.65) 34.975,22.625 v2(34.975,16.3)
VDD_3V3: ANA_A5_A6.3 C21.2 DIO_D9_D10.3 FR0.1 I2C.3 R2.1 R5.2 R6.2 XTAL.1 | length 84.8
  Top Layer w0.65: DIO_D9_D10.3 1.6,25.65 ; ANA_A5_A6.3@3.525,12.625 7.025,12.625 ; R6.2@5.55,46.375 R5.2 5.55,39.5 4.7,38.65 I2C.3 2.325,38.65 1.6,37.925 1.6,25.65 ; v2@18.325,12.625 7.025,12.625 ; v2(21.625,8.425) v2(22.25,7.8) 22.65,7.4 37.025,7.4 ; FR0.1 37,7.375 37.025,7.4 ; XTAL.1 40.875,7.4 37.025,7.4 ; 1.6,25.65 1.6,22.85 7.025,17.425 7.025,12.625
  Top Layer w0.8: ANA_A5_A6.3 ANA_A5_A6.3@3.525,12.625
  MidLayer2 w0.65: v2@18.375,12.625 18.375,11.675 v2(21.625,8.425) v2(22.25,7.8)
  other v2: 18.375,12.6
VDD_MBED: C22.2 C23.2 J3.4 R1.2 R2.2
VDD_RADIO: C16.2 C18.2 C20.2 R1.1 U1.1 U1.10 U1.11
  other v2: 37.875,29.8 32.45,30.475 37.875,30.5 32.45,31.25 32.1,31.95
VR_PA: C1.2 C2.2 L1.2 U1.24
XTA: Q1.3 U1.3 | length 6.8
  Top Layer w0.127: U1.3 35.45,28.45 v1(35.7,28.7)
  Top Layer w0.35: Q1.3 v1(35.875,33.7)
  MidLayer1 w0.127: v1(35.7,28.7) 35.7,29 35.475,29.225 35.475,33.325 v1@35.863,33.713
XTB: Q1.1 U1.4 | length 4.6
  Top Layer w0.127: v1(34.7,28.7) 34.95,28.45 U1.4
  Top Layer w0.35: v1(34.525,31.5) Q1.1
  MidLayer1 w0.127: v1(34.525,31.5) 34.9,31.125 34.9,29.197 34.7,28.997 v1(34.7,28.7)
  MidLayer1 w0.2: v1@34.5,31.475 v1(34.525,31.5)
pads on no net: J1.1 J1.2 J1.3 J1.5 J1.7 J2.8 J3.1 J3.2 J3.3 J3.5 J3.8

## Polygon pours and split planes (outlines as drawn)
GND on Top Layer "Top GND" (solid, remove dead copper, pour order 7): 0.25,0.25 64.751,0.25 64.751,53.05 0.25,53.05
GND on MidLayer1 "GND midlayer1" (solid, pour order 9): 0.25,0.25 64.733,0.25 64.733,53.05 0.25,53.05
GND on Bottom Layer "Bottom GND" (solid, pour order 10): 0.25,0.25 64.747,0.25 64.747,53.05 0.25,53.05
GND on MidLayer2 "GND midlayer2" (solid, pour order 8): 0.25,0.25 64.725,0.25 64.725,53.05 0.25,53.05

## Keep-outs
Keep-Out Layer:
  the board outline again, w0.05

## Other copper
Top Layer:
  region net GND: 20.88,10.04 20.88,11.915 21.45,11.915 21.45,10.04
  region net GND: 20.58,5.65 20.58,7.525 21.15,7.525 21.15,5.65
  region net GND: 17.72,5.1 17.72,12.17 16.825,12.17 16.825,5.1
  region net GND: 37.45,32.3 37.45,31.628 40.125,31.628 40.125,32.3
  pour cut-out: 55.75,0.35 57.025,0.8 58.473,1.479 58.65,1.575 58.667,1.575 58.813,1.663 59.275,1.95 59.3,1.975 59.61,2.158 59.725,2.25 59.75,2.275 60.225,2.625 60.3,2.7 60.325,2.725 60.698,3.027 60.773,3.102 61.898,4.227 62.011,4.339 62.706,5.196 62.851,5.399 63.175,5.95 63.3,6.15 63.55,6.55 63.664,6.781 63.85,7.1 63.935,7.332 64.103,7.673 64.225,8 64.338,8.304 64.468,8.653 64.563,8.92 64.669,9.193 64.75,9.4 64.9,9.4 64.9,0.2 64.875,0.175 55.725,0.175 55.725,0.35 55.75,0.375
  pour cut-out: 55.725,53.05 57.675,52.2 57.798,52.146 58.075,52.026 58.25,51.925 58.581,51.735 58.745,51.641 59.075,51.45 59.175,51.375 59.425,51.225 59.55,51.15 59.9,50.9 60.002,50.827 60.525,50.425 60.6,50.35 60.625,50.325 61.125,49.925 61.475,49.575 61.5,49.525 61.525,49.5 61.825,49.2 61.875,49.125 61.9,49.1 62.1,48.825 62.15,48.775 62.6,48.25 62.7,48.1 62.975,47.725 63.05,47.6 63.3,47.2 63.379,47.052 63.575,46.74 63.65,46.6 63.834,46.255 63.899,46.075 64.05,45.75 64.15,45.5 64.229,45.302 64.329,45.052 64.375,44.9 64.45,44.65 64.55,44.4 64.65,44.125 64.925,44.125 64.925,53.05 64.875,53.1 64.825,53.05
  region net VDD_RADIO: 19.15,22.9 23.625,27.375 23.85,27.375 23.85,25.325 20.725,22.2 19.85,22.2
  region net VDD_RADIO: 29.425,26.15 29.725,25.85 29.425,25.85
  region net VDD_RADIO: 23.725,27.25 23.85,27.375 26.85,27.375 27.55,28.075 27.55,30.575 28.275,31.3 32.775,31.3 32.775,29.575 29.7,29.575 29.45,29.325 29.45,25.875 31.775,25.875 31.775,25.162 31.085,24.5 27.825,24.5 27.8,24.5 26.95,25.325 23.725,25.325
  region net VDD_RADIO: 29.55,31.3 32.775,31.3 32.775,29.656 29.525,29.656 29.525,31.275
  region: 19.125,22.747
  region net VDD_RADIO: 19.15,22.905 20.75,22.905 20.75,9.525 20.475,9.25 19.15,9.25
  region net VDD_3V3: 18.85,9.248 18.85,12.752 18.652,12.95 17.877,12.95 17.625,12.698 17.625,12.473 17.85,12.248 17.85,9.248
  region net VDD_MBED: 18.575,1.725 19.675,1.725 20.45,2.5 20.45,8.7 17.85,8.7 17.85,2.45
  pour cut-out: 36.75,30.1 36.75,33.225 36.825,33.3 39.8,33.3 39.8,32.3 37.45,32.3 37.45,30.1
  pour cut-out: 30.75,32.275 32.9,32.275 32.9,28.1 37.4,28.1 37.4,31.075 34,31.075 34,33.275 30.75,33.275
  region net VDD_RADIO: 31.525,32.275 31.525,30 32.775,30 32.775,31.975 32.475,32.275
  region net GND: 35.8,26.875 35.8,28.225 36.1,28.525 36.1,28.815 36.225,28.94 36.475,28.94 36.6,28.815 36.6,28.6 36.44,28.44 36.315,28.44 36.15,28.275 36.15,26.875
  region net GND: 34.6,28.225 34.3,28.525 34.3,28.825 34.175,28.95 33.275,28.95 33.125,28.8 33.125,28.6 33.3,28.425 34.075,28.425 34.25,28.25 34.25,26.875 34.6,26.875
  pour cut-out: 38.3,29.05 41.048,29.05 41.05,29.048 41.05,29.02 38.3,29.02
  pour cut-out: 41.902,25.624 42.5,25.624 42.5,25.702 41.902,25.702
  region net GND: 39.975,24.575 39.975,25.95 41.898,25.95 42.227,25.624 51.525,25.624 51.525,25.1 40.7,25.1 40.7,24.575
  region net NetANT_1: 60.1,26.975 60.225,26.975 60.625,27.375 61.1,27.375 61.1,25.925 60.625,25.925 60.225,26.325 60.1,26.325
  pour cut-out: 64.8,23.475 60.5,23.475 60.5,29.825 64.8,29.825
  pour cut-out: 37.735,24.375 37.735,24.79 37.5,25.025 37.5,24.425 37.55,24.375
  region net GND: 51.975,22.525 51.975,23.75 53.1,23.75 53.1,23.25 52.35,23.25 52.35,22.525
  region net GND: 53.15,26.075 60.05,26.075 60.05,25.35 53.15,25.35
  region net GND: 50.55,28.05 44.075,28.05 44.075,29.075 44.475,29.075 44.475,28.625 50.55,28.625
  region net GND: 41.825,28.05 41.825,29 44.45,29 44.45,29.248 40.975,29.248 40.975,28.05
  region net GND: 38.351,31.85 38.351,29.05 41.381,29.05 41.381,29.875 39.025,29.875 39.025,31.85
  region net GND: 42.268,26.9 42.268,26.739 42.631,26.376 51.425,26.376 51.425,26.9
  region net VR_PA: 37.5,27.225 37.5,27.4 38.35,28.25 40.825,28.25 40.825,28.9 38.1,28.9 36.8,27.6 36.8,27.375 36.775,27.35 36.775,27.225
  region net NetL2_1: 37.15,26.575 37.625,26.575 38.2,27.15 38.775,27.15 38.775,27.8 38.125,27.8 38.125,27.575 37.425,26.875 37.15,26.875
  region net GND: 33.15,24.425 33.15,23.18 32.995,23.025 32.65,23.025 32.65,24.425
  region net GND: 36.1,25.375 37.635,25.375 38.305,24.705 38.305,24.6 37.908,24.6 37.483,25.025 36.1,25.025
  region net VDD_RADIO: 36.3,27.625 36.3,28.075 37.55,29.325 37.55,31.5 38.2,31.5 38.2,29.225 36.6,27.625
  region net GND: 31.65,27.625 31.65,26.925 32.425,26.925 32.8,26.55 34.3,26.55 34.3,26.925 32.925,26.925 32.75,27.1 32.75,27.4 32.525,27.625
  region net NetL7_2: 33.65,26.325 33.575,26.4 32.725,26.4 32.35,26.775 31.575,26.775 31.35,27 31.35,27.625 29.75,27.625 29.75,26.05 33.575,26.05 33.65,26.125
  region net NetC17_2: 29.75,29.325 32.175,29.325 32.95,28.55 32.95,27.975 29.75,27.975
  region net NetC17_2: 31.85,29.325 32.175,29.325 33.55,27.95 33.55,27.225 32.9,27.225 32.9,27.475 31.849,28.526
  pour cut-out: 36.586,24.65 36.542,24.65 33.8,24.65 33.802,24.519 36.586,24.519
  pour cut-out: 36.586,24.6 36.45,24.6 36.45,27.3 33.775,27.3 33.775,27.424 36.58,27.427 36.582,27.425
  pour cut-out: 33.925,27.4 33.925,24.625 33.775,24.625 33.775,27.4
  region net VDD_RADIO: 31.65,25.075 33.3,25.075 33.3,25.375 33,25.375 32.95,25.425 32.95,25.525 33,25.575 33.3,25.575 33.3,25.875 31.65,25.875
  region net GND: 31.04,24.175 31.79,24.925 32.75,24.925 32.75,24.7 32.7,24.65 31.875,24.65 31.725,24.5 31.725,24.175
  region net GND: 52.025,30.925 52.55,30.925 52.55,30.175 53.05,30.175 53.05,29.55 52.025,29.55
  region net GND: 60.12,26.075 60.3,25.895 60.3,25.48 60.5,25.48 60.5,23.275 59.9,23.27 59.9,26.075
  pour cut-out: 41.825,28.025 41.825,29.001 44.072,29.001 44.075,28 44.025,28 44.025,28.95 41.875,28.95 41.875,28.025
  pour cut-out: 44.025,28.05 50.15,28.05 50.153,28.047 50.153,27.8 50.117,27.8 50.117,28 50.05,28 44.025,28
  pour cut-out: 38.106,24.848 39.975,24.848 39.975,26.05 39.9,26.05 39.9,24.92 39.855,24.965 38.106,24.965
  pour cut-out: 42.175,26.9 51.147,26.9 51.15,26.897 51.15,26.953 42.178,26.953 42.175,26.95
  pour cut-out: 52.8,27.751 53.15,27.75 53.15,27.226 55.175,27.226 55.175,27.026 56.324,27.026 56.325,27.226 60.25,27.226 60.25,27.15 56.4,27.15 56.4,26.975 55.1,26.975 55.1,27.15 53.075,27.15 53.072,27.675 52.8,27.675
  pour cut-out: 52.75,25.549 53.15,25.549 53.15,26.073 55.17,26.075 55.17,26.275 56.296,26.275 56.3,26.075 60.298,26.075 60.299,26.15 56.425,26.15 56.425,26.325 55.1,26.325 55.1,26.175 53.05,26.175 53.05,25.675 52.75,25.675
  pour cut-out: 51.797,25.549 51.793,27.75 52.125,27.751 52.125,27.625 51.95,27.625 51.95,25.6 52.1,25.6 52.1,25.549
  pour cut-out: 60.299,27.2 60.299,27.85 60.525,27.85 60.525,27.78 60.375,27.78 60.375,27.2
MidLayer2:
  pour cut-out: 64.8,23.475 60.5,23.475 60.5,29.825 64.8,29.825
  pour cut-out: 55.625,53.075 58.75,51.675 60.292,50.624 62.35,48.6 62.475,48.4 62.868,47.845 62.975,47.7 63.222,47.323 63.332,47.154 63.475,46.875 63.55,46.775 63.7,46.5 63.773,46.324 63.889,46.069 63.985,45.855 64.115,45.595 64.2,45.35 64.285,45.104 64.375,44.9 64.418,44.722 64.47,44.573 64.521,44.424 64.6,44.15 64.65,44.033 64.725,43.8 64.8,43.625 64.9,43.625 64.9,53.075 64.875,53.1 64.85,53.075
  pour cut-out: 55.725,0.325 57.1,0.85 58.503,1.47 58.875,1.7 59.076,1.824 59.575,2.15 59.74,2.26 60.363,2.737 60.5,2.85 62.187,4.56 62.288,4.687 62.753,5.273 62.85,5.425 63.151,5.899 63.275,6.1 63.493,6.454 63.6,6.65 63.75,6.925 63.875,7.2 63.975,7.45 64.125,7.75 64.229,7.979 64.325,8.275 64.425,8.525 64.525,8.825 64.6,9.05 64.718,9.402 64.875,9.675 64.9,9.65 64.9,0.175 55.725,0.175
  pour cut-out: 36.75,30.1 36.75,33.225 36.825,33.3 39.8,33.3 39.8,32.3 37.45,32.3 37.45,30.1
  pour cut-out: 30.75,32.275 32.9,32.275 32.9,29.475 37.45,29.475 37.45,31.075 33.75,31.075 33.75,33.2 33.675,33.275 30.75,33.275
  region net GND: 33.8,27.375 33.8,24.575 36.6,24.575 36.6,27.375
MidLayer1:
  pour cut-out: 64.8,23.475 60.5,23.475 60.5,29.825 64.8,29.825
  pour cut-out: 55.625,53.1 56.187,52.813 57.15,52.475 57.4,52.4 57.7,52.25 57.925,52.15 58.225,51.975 58.425,51.9 58.775,51.7 58.95,51.6 59.245,51.38 59.425,51.275 59.975,50.9 60.1,50.8 60.573,50.422 60.647,50.347 61.425,49.6 61.776,49.218 61.847,49.147 62.425,48.475 62.5,48.375 62.875,47.875 62.95,47.75 63.175,47.4 63.25,47.3 63.43,47.003 63.493,46.846 63.7,46.5 63.775,46.325 63.904,46.077 64.025,45.825 64.125,45.575 64.2,45.375 64.275,45.175 64.376,44.925 64.45,44.675 64.6,44.225 64.65,44.075 64.725,43.85 64.775,43.75 64.85,43.725 64.85,53.1 55.625,53.1 55.924,52.947 56.1,52.9 56.318,52.758 56.675,52.7 56.775,52.65 56.925,52.625
  pour cut-out: 55.775,0.325 55.895,0.362 56.1,0.45 56.275,0.525 56.356,0.56 56.544,0.64 56.697,0.706 56.925,0.775 57.1,0.85 57.296,0.934 57.903,1.194 57.923,1.198 58.099,1.278 58.225,1.35 58.25,1.35 58.499,1.478 58.6,1.55 58.847,1.705 59,1.8 59.25,1.95 59.35,2 59.382,2.039 59.468,2.093 59.575,2.15 59.9,2.4 60.015,2.488 60.7,3.025 60.75,3.075 61.35,3.675 61.375,3.7 62.1,4.45 62.186,4.539 62.675,5.15 62.75,5.275 62.975,5.6 63.058,5.72 63.225,6 63.3,6.1 63.45,6.375 63.527,6.506 63.7,6.8 63.782,6.996 63.875,7.2 63.944,7.353 64.025,7.525 64.12,7.727 64.2,7.925 64.272,8.101 64.35,8.3 64.435,8.546 64.5,8.75 64.58,8.999 64.628,9.149 64.7,9.35 64.7,9.525 64.789,9.575 64.9,9.6 64.875,9.575 64.875,0.175 55.775,0.175
  region net GND: 35.114,33.425 35.114,28.375 35.261,28.375 35.261,33.425
  pour cut-out: 37.45,29.475 35.35,29.475 35.35,30.775 37.45,30.775
  pour cut-out: 33.975,31.075 33.975,30.55 37.125,30.55 37.125,31.075
  pour cut-out: 36.75,30.1 36.75,33.226 36.824,33.3 39.8,33.3 39.8,32.3 37.45,32.3 37.45,30.1
  pour cut-out: 30.75,32.275 32.9,32.275 32.9,29.475 35.025,29.475 35.025,31.075 33.75,31.075 33.75,33.2 33.675,33.275 30.75,33.275
  region net GND: 33.7,27.5 33.7,24.475 36.643,24.475 36.643,27.5
Bottom Layer:
  pour cut-out: 55.6,53.05 56.8,52.6 58.6,51.775 58.75,51.675 59.05,51.5 59.171,51.394 59.604,51.106 59.725,51.025 60.275,50.625 60.375,50.525 62.196,48.722 62.312,48.587 62.775,47.975 62.83,47.88 63.05,47.55 63.17,47.395 63.387,47.037 63.465,46.91 63.6,46.675 63.6,46.65 63.666,46.559 63.775,46.325 63.869,46.122 63.999,45.849 64.099,45.625 64.2,45.35 64.262,45.18 64.32,45.023 64.385,44.845 64.448,44.674 64.529,44.451 64.575,44.325 64.664,44.08 64.7,43.925 64.775,43.7 64.85,43.675 64.9,53.1 55.6,53.1
  pour cut-out: 55.75,0.325 56.975,0.775 58.588,1.562 58.775,1.675 59.213,1.938 59.418,2.061 60.025,2.475 60.406,2.735 61.811,4.173 62.413,4.862 62.867,5.481 62.979,5.621 63.25,6.05 63.337,6.237 63.575,6.625 63.709,6.844 63.875,7.2 63.992,7.468 64.125,7.775 64.22,8.077 64.334,8.332 64.437,8.594 64.516,8.794 64.625,9.15 64.678,9.324 64.763,9.6 64.925,9.625 64.9,9.6 64.9,0.175 55.775,0.175 55.75,0.2
  pour cut-out: 36.75,30.1 36.75,33.225 36.825,33.3 39.8,33.3 39.8,32.3 37.45,32.3 37.45,30.1
  pour cut-out: 30.75,32.275 32.85,32.275 32.85,29.475 37.45,29.475 37.45,31.075 33.75,31.075 33.75,33.2 33.675,33.275 30.75,33.275
  region net VDD_RADIO: 31.75,32.275 31.75,29.1 38.225,29.1 38.225,31.026 37.525,31.029 37.525,29.475 32.825,29.475 32.825,32.275
  region net GND: 33.75,27.375 33.75,24.575 36.65,24.575 36.65,27.375

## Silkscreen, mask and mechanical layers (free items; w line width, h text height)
Top Overlay:
  lines w0.15: 53.2,25.975 53.2,22.525 29.475,22.525 29.475,33.7 53.2,33.7 53.2,27.325
  text "1" at 48.55,50.375 h1
  text "1" at 26.925,50.325 h1
  text "J2" at 24.175,47.75 h1.27
  text "J1" at 46.225,47.65 h1.27
  text "Sensors" at 1.1,47.4 h1.4
  text "SX1262MB2xAS mbed shield" at 23.3,44.25 h1.5
  text "SCL SDA" at 6.5,44 h0.8 r270
  text "PCB_E499V01B 3118" at 31,41.25 h1.27
  text "SX1262" at 45.224,34.275 h1.4
  text "D9 D10" at 6.5,30.5 h0.8 r270
  text "A5 A6" at 6.5,17.5 h0.8 r270
  text "Freq Band:" at 49.75,12.625 h1.27
  text "J3" at 10.225,4.475 h1.27
  text "J4" at 33.25,4.4 h1.27
  text "1" at 9.425,2.175 h1
  text "1" at 32.675,2.175 h1
Bottom Overlay:
  text "RoHS" at 11.794,29.37 h2.2 r270
  text "compliant" at 10.244,27.32 h2.2 r270
  text "PCB_E499V01B 3118" at 0.75,17.7 h1.27 r270
Bottom Solder:
  region: 33.9,27.275 33.9,24.675 36.5,24.675 36.5,27.275
Mechanical 3:
  text "Origin(0;0)" at -10.425,-1.9 h1
Mechanical 14:
  the board outline again, w0.05

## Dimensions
0,0 to 65,0 on Mechanical 3
0,53.3 to 0,0 on Mechanical 3
52.3,40.6 to 66.852,55.152 on Mechanical 3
